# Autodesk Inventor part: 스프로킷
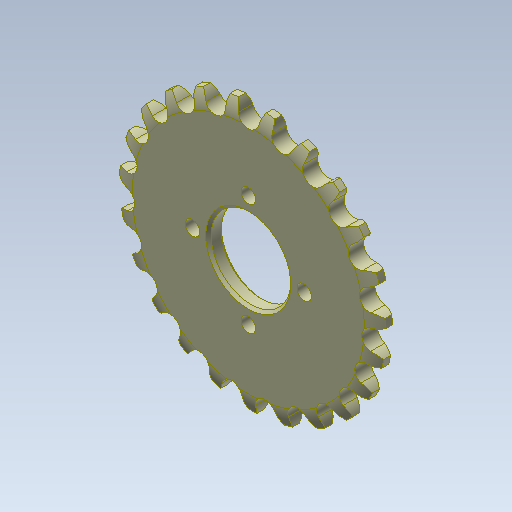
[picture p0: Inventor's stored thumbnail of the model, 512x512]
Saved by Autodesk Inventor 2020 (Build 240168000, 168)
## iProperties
Created: 2024-02
Part Number: 스프로킷
Material: 강철, 합금
Document SubType Name: Modeling
Designer: mdu-01
Density: 1 g/cm^3
Appearance: 기본값(1)
Author: mdu-01
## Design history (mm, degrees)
sketch "스케치1"
  geometry: L1 (0, 2.9)-(0, -2.9); L2 (16, 2.9)-(43.6, 2.9); L3 (50, 1.287)-(50, -1.287); L4 (43.6, -2.9)-(16, -2.9); L5 (15, -1.9)-(15, 1.9); L6 (15, 0)-(50, 0); L7 (16, 2.9)-(15, 1.9); L8 (16, -2.9)-(15, -1.9); A1 r 13.5 centre (43.6, -10.6) between (50, 1.287) and (43.6, 2.9); A2 r 13.5 centre (43.6, 10.6) between (43.6, -2.9) and (50, -1.287); 4 further points
  constraints: 16 end point, 6 point on line, 4 point on circle, 3 midpoint, 3 symmetric about line, 2 centre point, 2 parallel, 1 coincident, 1 horizontal, 1 perpendicular, 1 tangent, 1 vertical, 1 other
  dimensions: "d0" = 5.8 distance of L1.start L1.end; "d2" = 100 diameter of L3 L1; "d3" = 30 diameter of L5 L1; "d4" = 6.4 distance from line of A1.centre L3; "d5" = 13.5 radius of A1; "d8" = 1 distance of point (15, 2.9) L5.end; "d9" = 1 distance of L2.start point (15, 2.9); "d10" = 1 distance of L4.end point (15, -2.9)
revolve "회전1" sketch "스케치1" stored, may be unused: angle "d11" = 90 deg
sketch "스케치2"
  geometry: A1 r 46.635 centre (0, 0) between (0, 46.635) and (12.582, 44.906); A2 r 3.885 centre (0, 46.635) between (-3.849, 46.106) and (3.849, 46.106); A3 r 12.7 centre (0, 46.635) between (12.582, 44.906) and (-12.582, 44.906); A4 r 8.815 centre (12.582, 44.906) between (17.817, 51.998) and (3.849, 46.106); A5 r 8.815 centre (-12.582, 44.906) between (-17.817, 51.998) and (-3.849, 46.106); A6 r 30 centre (0, 27.862) between (17.817, 51.998) and (-17.817, 51.998); 1 further point
  constraints: 13 point on circle, 6 centre point, 4 tangent, 2 coincident, 1 vertical alignment
  dimensions: "d12" = 93.27 diameter of A1; "d13" = 7.77 diameter of A2; "d14" = 25.4 diameter of A3; "d15" = 30 radius of A6
extrude "돌출1" cut sketch "스케치2" extent not by distance; stored distance "d16" = 10; taper "d17" = 0 deg
sketch "스케치3" dims "d21" = 42
  geometry: 3 further points
  constraints: 2 vertical alignment, 1 coincident, 2 other
hole "구멍1" sketch "스케치3" at (0, -25.635) diameter "d22" = 5.5; stored, may be unused: countersink angle "d26" = 90 deg, drill point angle "d28" = 118 deg; dims "d23" = 6, "d24" = 9.4, "d25" = 2, "d27" = 8
node "솔리드1"
pattern_circular "원형 패턴1" dims angle "d19" = 360 deg
pattern_circular "원형 패턴2" dims angle "d30" = 360 deg
